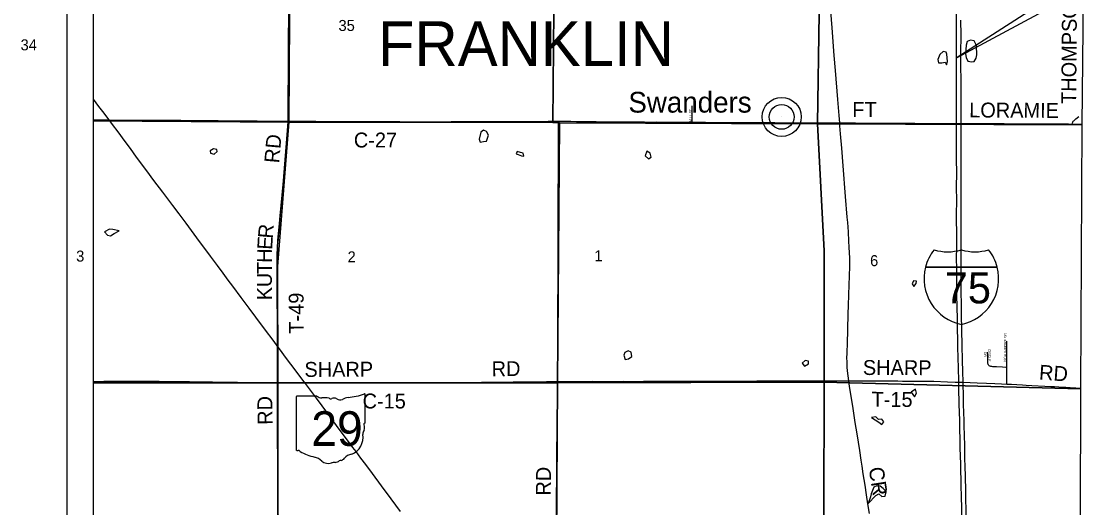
# Model space of a CAD drawing. Extents: x -784 to 1375, y -225 to 440.
# Drawn here: x 438.7 to 519.3, y 324.9 to 362 of the extents above; entities that cross this region are included whole.
import ezdxf

# ---------------------------------------------------------------- set-up
doc = ezdxf.new("R2010")
doc.units = 0
for name, color, linetype in [('GM_X_County_Road', 7, 'Continuous'), ('GM_X_County_Road_Text', 7, 'Continuous'), ('GM_X_Interstate_Location', 7, 'Continuous'), ('GM_X_Interstate_Route', 7, 'Continuous'), ('GM_X_Interstate_Shield', 7, 'Continuous'), ('GM_X_Minor_Lake', 7, 'Continuous'), ('GM_X_Section', 7, 'Continuous'), ('GM_X_Section_Text', 7, 'Continuous'), ('GM_X_State_Location', 7, 'Continuous'), ('GM_X_State_Route', 7, 'Continuous'), ('GM_X_State_Shield', 7, 'Continuous'), ('GM_X_Township', 7, 'Continuous'), ('GM_X_Township_Road', 7, 'Continuous'), ('GM_X_Township_Road_Text', 7, 'Continuous'), ('GM_X_Township_Subdivision', 7, 'Continuous'), ('GM_X_Township_Subdivision_Text', 7, 'Continuous'), ('GM_X_Township_Text', 7, 'Continuous'), ('GM_X_Unincorporated', 7, 'Continuous'), ('GM_X_Unincorporated_Location', 7, 'Continuous'), ('GM_X_Unincorporated_Text', 7, 'Continuous'), ('SH_Data', 7, 'Continuous'), ('SH_Text', 7, 'Continuous')]:
    doc.layers.add(name, color=color, linetype=linetype)

msp = doc.modelspace()

# ---------------------------------------------------------------- linework, layer by layer
at = {"layer": 'GM_X_County_Road'}
for points in [[(501.121, 354.211), (501.079, 354.768), (500.983, 356.007), (500.808, 358.2), (500.712, 359.339), (500.545, 361.445), (500.497, 362.077), (500.361, 363.774), (500.311, 364.381), (500.247, 365.161), (500.16, 366.276), (500.065, 367.403), (499.97, 368.604), (499.898, 369.459), (499.82, 370.487), (499.762, 371.134)], [(444.236, 354.441), (444.598, 354.437), (445.095, 354.439), (445.344, 354.439), (445.419, 354.437)], [(445.419, 354.437), (445.803, 354.43), (446.636, 354.421), (447.729, 354.417), (448.835, 354.416), (449.618, 354.418), (449.979, 354.42), (450.488, 354.414), (450.911, 354.41), (451.619, 354.406), (452.203, 354.396), (452.713, 354.391), (453.235, 354.387), (453.769, 354.386), (455.434, 354.372), (456.727, 354.361), (457.932, 354.353), (458.802, 354.352), (458.976, 354.349), (459.122, 354.347)], [(459.122, 354.347), (460.628, 354.338), (461.2, 354.334), (461.784, 354.33), (462.554, 354.325), (462.927, 354.324), (463.138, 354.324), (463.586, 354.323), (463.859, 354.322), (465.549, 354.314), (466.394, 354.314), (466.804, 354.313), (467.612, 354.31), (468.768, 354.304), (469.974, 354.306), (471.527, 354.31), (471.925, 354.31), (472.285, 354.31), (472.894, 354.317), (473.714, 354.313), (474.484, 354.313), (475.156, 354.314), (475.901, 354.314), (476.485, 354.323), (477.106, 354.328), (477.492, 354.33), (477.827, 354.33), (478.896, 354.332), (479.654, 354.332), (479.708, 354.332)], [(479.708, 354.332), (480.201, 354.335), (480.623, 354.333), (481.071, 354.328), (481.53, 354.324), (482.562, 354.31), (483.32, 354.303), (483.904, 354.299), (484.674, 354.293), (485.159, 354.29), (485.544, 354.287), (485.805, 354.284), (486.24, 354.281), (486.836, 354.28), (487.197, 354.281), (487.793, 354.277), (488.588, 354.268), (488.973, 354.26), (489.887, 354.257)], [(489.887, 354.257), (490.711, 354.257), (490.907, 354.256)], [(490.907, 354.256), (491.246, 354.255), (491.668, 354.253), (492.401, 354.253), (493.085, 354.253), (493.358, 354.25), (493.52, 354.246), (493.917, 354.247), (494.526, 354.24), (494.638, 354.238), (494.96, 354.236), (495.184, 354.237), (495.828, 354.236), (496.188, 354.233), (496.499, 354.23), (497.046, 354.223), (497.642, 354.222), (499.221, 354.222), (500.203, 354.219), (500.662, 354.216), (501.121, 354.211)], [(501.814, 334.565), (501.763, 334.947), (501.723, 335.318), (501.702, 335.603), (501.683, 335.976), (501.675, 336.337), (501.679, 336.623), (501.704, 337.53), (501.731, 338.325), (501.748, 338.847), (501.761, 339.282), (501.774, 339.692), (501.793, 340.288), (501.823, 341.145), (501.892, 343.281), (501.896, 343.628), (501.891, 343.926), (501.874, 344.323), (501.85, 344.757), (501.828, 345.191), (501.781, 345.923), (501.73, 346.617), (501.696, 347.038), (501.573, 348.611), (501.384, 350.94), (501.275, 352.278), (501.187, 353.38), (501.137, 353.987), (501.121, 354.211)], [(501.121, 354.211), (501.139, 354.211), (501.395, 354.209), (501.805, 354.208), (502.328, 354.206), (502.986, 354.202), (503.645, 354.198), (504.726, 354.192), (505.521, 354.188), (506.019, 354.182), (506.565, 354.18), (506.839, 354.183), (507.137, 354.176), (507.621, 354.171), (508.168, 354.172), (509.161, 354.168), (509.608, 354.166), (510.033, 354.164), (510.367, 354.163), (511.783, 354.158), (512.491, 354.155), (513, 354.156), (513.659, 354.155), (514.33, 354.148), (514.778, 354.145), (515.312, 354.145), (515.535, 354.144), (515.921, 354.143), (516.517, 354.139), (517.027, 354.136), (517.66, 354.134), (518.218, 354.132), (518.566, 354.13), (518.843, 354.126)], [(518.843, 354.126), (518.952, 354.125), (519.511, 354.121), (519.555, 354.12)], [(460.336, 334.419), (460.676, 334.426), (461.26, 334.424), (461.894, 334.424), (462.54, 334.424), (463.149, 334.421), (464.081, 334.419), (465.237, 334.413), (466.032, 334.415), (466.679, 334.417), (467.225, 334.422), (467.523, 334.422), (467.921, 334.424), (468.206, 334.422), (468.492, 334.421), (468.927, 334.42), (469.337, 334.419), (469.909, 334.423), (470.219, 334.422), (471.052, 334.429), (471.723, 334.432), (472.108, 334.44), (472.506, 334.439), (472.916, 334.441), (473.388, 334.448), (473.835, 334.45), (474.307, 334.457), (474.966, 334.467), (475.363, 334.469), (475.761, 334.475), (476.233, 334.479), (476.531, 334.487), (477.177, 334.491), (477.861, 334.494), (478.768, 334.504), (479.63, 334.514)], [(479.63, 334.514), (480.098, 334.52), (480.657, 334.524), (481.129, 334.52), (482.273, 334.526), (483.142, 334.525), (483.851, 334.523), (484.683, 334.529), (484.919, 334.524), (486.175, 334.53), (487.194, 334.542), (487.964, 334.539), (488.536, 334.539), (489.568, 334.536), (490.04, 334.536), (490.786, 334.539), (491.419, 334.544), (491.904, 334.546), (492.625, 334.547), (493.184, 334.549), (493.88, 334.551), (494.8, 334.553), (495.843, 334.56), (496.377, 334.568), (497.235, 334.565), (497.744, 334.559), (498.366, 334.555), (499.334, 334.558), (500.005, 334.563), (500.34, 334.565), (500.775, 334.569), (501.198, 334.574), (501.571, 334.574), (501.814, 334.565)], [(503.389, 324.459), (503.275, 325.183), (503.167, 325.871), (503.055, 326.608), (502.917, 327.479), (502.83, 328.057), (502.756, 328.523), (502.644, 329.26), (502.442, 330.524), (502.309, 331.384), (502.138, 332.464), (501.875, 334.146), (501.822, 334.503), (501.814, 334.565)]]:
    msp.add_lwpolyline(points, dxfattribs=at)
at = {"layer": 'GM_X_Interstate_Route'}
for points in [[(510.447, 323.738), (510.394, 325.826), (510.379, 326.496), (510.34, 328.236), (510.31, 329.441), (510.265, 331.553), (510.232, 332.796), (510.203, 334.038), (510.194, 334.462), (510.166, 335.641), (510.152, 336.25), (510.134, 337.206), (510.092, 339.008), (510.062, 340.462), (510.055, 340.847), (510.04, 342.102), (510.037, 343.121), (510.033, 343.879), (510.035, 344.773), (510.037, 345.482), (510.033, 347.184), (510.036, 348.352), (510.033, 349.26), (510.034, 350.453), (510.032, 351.397), (510.032, 353.212), (510.033, 354.164), (510.031, 355.237), (510.033, 356.666), (510.029, 358.133), (510.027, 358.779), (510.031, 359.922), (510.028, 361.588), (510.026, 362.706)], [(510.77, 324.222), (510.727, 326.049), (510.696, 327.391), (510.68, 327.925), (510.673, 328.198), (510.666, 328.484), (510.645, 329.478), (510.619, 330.559), (510.607, 331.018), (510.601, 331.279), (510.595, 331.553), (510.567, 332.758), (510.56, 333.019), (510.553, 333.304), (510.525, 334.45), (510.504, 335.267), (510.488, 336.125), (510.465, 337.28), (510.41, 339.591), (510.395, 340.275), (510.39, 340.585), (510.385, 341.132), (510.381, 341.468), (510.375, 342.226), (510.374, 342.885), (510.374, 343.531), (510.372, 344.016), (510.368, 345.345), (510.365, 345.929), (510.367, 347.619), (510.368, 348.117), (510.369, 348.589), (510.369, 348.937), (510.367, 349.546), (510.366, 350.117), (510.368, 350.813), (510.369, 351.236), (510.369, 351.348), (510.37, 351.621), (510.37, 351.845), (510.37, 351.894), (510.37, 352.093), (510.37, 353.211), (510.367, 354.163), (510.366, 355.66), (510.365, 356.356), (510.365, 357.101), (510.365, 357.362), (510.362, 358.642), (510.359, 359.09), (510.361, 359.525), (510.365, 360.892), (510.364, 362.035)]]:
    msp.add_lwpolyline(points, dxfattribs=at)
at = {"layer": 'GM_X_Interstate_Shield'}
for p, q in [((507.659, 343.215), (513.124, 343.215)), ((513.124, 343.215), (507.659, 343.215)), ((513.124, 343.215), (507.659, 343.215))]:
    msp.add_line(p, q, dxfattribs=at)
for centre, start, end in [((511.101, 342.345), 141.66896, 165.80665), ((509.353, 347.943), 253.00908, 286.99093), ((511.429, 347.943), 253.00908, 286.99093), ((509.681, 342.345), 14.19335, 38.33104), ((511.101, 342.345), 165.80665, 258.46304), ((509.681, 342.345), 281.53696, 14.19335)]:
    msp.add_arc(centre, 3.551, start, end, dxfattribs=at)
at = {"layer": 'GM_X_Minor_Lake'}
for p, q in [((453.139, 352.094), (453.188, 351.903)), ((453.685, 352.022), (453.657, 352.189)), ((476.537, 352.034), (476.466, 351.868)), ((477.062, 351.683), (476.99, 351.897)), ((486.745, 351.602), (486.682, 351.913)), ((476.466, 351.868), (476.631, 351.798)), ((506.65, 341.943), (506.768, 341.751)), ((506.939, 341.983), (506.965, 342.156)), ((484.676, 336.526), (484.769, 336.184)), ((498.257, 335.915), (498.45, 335.684)), ((498.735, 335.86), (498.731, 336.057)), ((504.487, 331.445), (504.339, 331.645))]:
    msp.add_line(p, q, dxfattribs=at)
for points in [[(511.553, 360.075), (511.498, 360.214), (511.358, 360.46), (511.093, 360.503), (510.833, 360.41), (510.76, 360.139), (510.709, 359.482)], [(510.709, 359.482), (510.758, 359.185), (510.897, 358.917), (511.178, 358.873), (511.376, 358.899), (511.525, 359.139), (511.567, 359.388), (511.553, 360.075)], [(509.286, 359.45), (509.237, 359.611), (508.995, 359.646), (508.74, 359.432), (508.601, 359.03)], [(508.601, 359.03), (508.66, 358.797), (508.896, 358.8), (509.17, 358.832), (509.265, 358.626), (509.323, 358.89), (509.286, 359.45)], [(474.362, 353.27), (474.215, 353.558), (473.973, 353.661), (473.781, 353.514), (473.659, 352.972)], [(473.659, 352.972), (473.714, 352.735), (473.973, 352.806), (474.217, 352.824), (474.362, 353.27)], [(453.657, 352.189), (453.392, 352.225), (453.139, 352.094)], [(453.188, 351.903), (453.453, 351.83), (453.685, 352.022)], [(476.99, 351.897), (476.793, 351.946), (476.537, 352.034)], [(486.682, 351.913), (486.427, 352.063), (486.31, 351.713)], [(476.631, 351.798), (476.865, 351.702), (477.062, 351.683)], [(486.31, 351.713), (486.545, 351.469), (486.745, 351.602)], [(446.226, 345.999), (445.741, 346.092), (445.491, 346.105), (445.1, 345.908)], [(445.1, 345.908), (445.331, 345.669), (445.566, 345.619), (445.834, 345.78), (446.226, 345.999)], [(506.965, 342.156), (506.738, 342.191), (506.65, 341.943)], [(506.768, 341.751), (506.939, 341.983)], [(485.28, 336.426), (485.228, 336.757), (485.009, 336.853), (484.756, 336.729), (484.676, 336.526)], [(484.769, 336.184), (485.036, 336.239), (485.28, 336.426)], [(498.731, 336.057), (498.481, 336.122), (498.257, 335.915)], [(498.45, 335.684), (498.735, 335.86)], [(506.976, 333.62), (506.888, 333.94), (506.556, 333.708)], [(506.556, 333.708), (506.809, 333.351), (506.976, 333.62)], [(504.339, 331.645), (504.072, 331.628), (503.87, 331.814), (503.553, 331.774)], [(503.553, 331.774), (504.091, 331.423), (504.339, 331.229), (504.487, 331.445)], [(504.67, 326.119), (504.443, 326.364), (504.195, 326.528), (503.952, 326.556), (503.715, 326.454), (503.627, 326.222), (503.516, 325.959), (503.458, 325.717), (503.297, 325.218)], [(503.297, 325.218), (503.871, 325.83), (504.109, 325.962), (504.341, 325.745), (504.592, 325.77), (504.67, 326.119)]]:
    msp.add_lwpolyline(points, dxfattribs=at)
at = {"layer": 'GM_X_Section'}
for p, q in [((444.236, 364.18), (444.236, 354.38)), ((444.236, 354.38), (444.236, 334.405)), ((444.236, 334.405), (444.236, 314.304))]:
    msp.add_line(p, q, dxfattribs=at)
for points in [[(506.617, 371.896), (519.776, 373.558), (519.562, 354.071), (499.42, 354.13), (499.684, 371.026)], [(499.684, 371.026), (499.42, 354.13), (479.771, 354.211), (479.249, 354.244), (479.388, 368.483), (486.548, 369.394)], [(466.358, 366.879), (479.388, 368.483), (479.249, 354.244), (459.168, 354.279), (459.245, 366.065)], [(459.168, 354.279), (479.249, 354.244), (479.771, 354.211), (479.62, 334.419), (458.333, 334.409), (458.294, 343.266)], [(479.771, 354.211), (499.42, 354.13), (499.944, 344.47), (499.931, 334.47), (479.62, 334.419)], [(519.562, 354.071), (519.48, 333.952), (499.931, 334.47), (499.944, 344.47), (499.42, 354.13)], [(458.333, 334.409), (479.62, 334.419), (479.486, 314.324), (458.351, 314.341)], [(479.62, 334.419), (499.931, 334.47), (499.901, 324.411), (499.543, 314.191), (479.486, 314.324)], [(519.48, 333.952), (519.411, 314.122), (499.543, 314.191), (499.901, 324.411), (499.931, 334.47)]]:
    msp.add_lwpolyline(points, close=True, dxfattribs=at)
for points in [[(444.236, 354.38), (459.168, 354.279), (459.245, 366.065), (446.077, 364.411), (444.236, 364.18)], [(444.236, 334.405), (458.333, 334.409), (458.294, 343.266), (459.168, 354.279), (444.236, 354.38)], [(444.236, 314.304), (458.351, 314.341), (458.333, 334.409), (444.236, 334.405)]]:
    msp.add_lwpolyline(points, dxfattribs=at)
at = {"layer": 'GM_X_State_Route'}
for points in [[(444.236, 356.029), (444.649, 355.468), (444.937, 355.078), (445.34, 354.542), (445.419, 354.437), (445.609, 354.184), (446.186, 353.421), (446.577, 352.89), (447.042, 352.261), (447.523, 351.612), (448.31, 350.555), (448.843, 349.837), (449.521, 348.932), (450.273, 347.927), (450.758, 347.281), (451.294, 346.564), (452.109, 345.467), (453.148, 344.071), (453.682, 343.353), (454.11, 342.773), (454.502, 342.244), (454.852, 341.776), (455.49, 340.919), (456.097, 340.101), (456.617, 339.403), (457.349, 338.414), (457.913, 337.657), (458.303, 337.136), (458.405, 337.001), (458.952, 336.276), (459.599, 335.41), (460.336, 334.419)], [(444.236, 334.518), (445.041, 334.526), (445.775, 334.531), (448.16, 334.544), (449.266, 334.538), (450.397, 334.522), (451.031, 334.515), (451.578, 334.509), (452.149, 334.498), (452.745, 334.488), (453.317, 334.484), (455.231, 334.467), (457.853, 334.436), (458.321, 334.433), (459.133, 334.43), (460.177, 334.421), (460.336, 334.419)], [(460.336, 334.419), (460.378, 334.363), (460.842, 333.748), (461.218, 333.238), (461.655, 332.65), (462.22, 331.893), (462.965, 330.882), (463.58, 330.054), (464.008, 329.49), (464.248, 329.173), (464.618, 328.675), (464.975, 328.196), (465.493, 327.498), (466.187, 326.558), (466.924, 325.573), (467.27, 325.102), (467.638, 324.602)]]:
    msp.add_lwpolyline(points, dxfattribs=at)
at = {"layer": 'GM_X_State_Shield'}
for p, q in [((461.29, 333.399), (459.745, 333.399)), ((464.967, 331.404), (464.967, 333.498)), ((459.693, 333.33), (459.693, 329.327)), ((464.966, 331.405), (464.967, 331.404))]:
    msp.add_line(p, q, dxfattribs=at)
for centre, radius, start, end in [((459.754, 333.338), 0.0611, 98.1301, 188.1301), ((461.657, 333.863), 0.593, 231.61951, 271.11188), ((463.088, 338.855), 5.592, 275.84447, 288.90645), ((464.908, 333.507), 0.0587, 351.86209, 97.738), ((461.854, 331.152), 2.127, 80.48669, 94.98827), ((462.337, 333.359), 0.171, 219.79206, 297.10237), ((462.588, 332.896), 0.355, 54.46668, 119.14113), ((463.046, 333.531), 0.428, 233.85621, 294.82819), ((463.802, 332.176), 1.125, 97.34618, 120.76885), ((464.953, 331.25), 0.0909, 107.94398, 210.33697), ((464.375, 330.986), 0.545, 340.03296, 23.64957), ((464.904, 331.396), 0.0628, 289.60381, 7.73413), ((463.402, 330.262), 1.399, 292.30889, 8.98584), ((465.177, 330.528), 0.397, 136.8065, 186.92959), ((459.754, 329.319), 0.0616, 171.95839, 258.30661), ((459.764, 329.728), 0.47, 267.33899, 280.60386), ((459.86, 329.097), 0.17, 29.74838, 93.27175), ((462.001, 332.692), 4.038, 240.41292, 257.1985), ((460.797, 327.529), 1.264, 47.18416, 75.83597), ((463.021, 328.939), 0.452, 282.87319, 323.27711), ((463.991, 328.204), 0.766, 94.40312, 142.57675), ((462.164, 329.077), 0.802, 230.70037, 286.29184), ((462.627, 327.693), 0.659, 85.69512, 111.20995), ((462.686, 328.777), 0.427, 268.77702, 315.54927), ((463.072, 328.389), 0.12, 65.75173, 132.64842)]:
    msp.add_arc(centre, radius, start, end, dxfattribs=at)
at = {"layer": 'GM_X_Township'}
for points in [[(444.236, 382.734), (444.236, 283.309), (458.267, 283.309)], [(458.267, 283.309), (458.263, 284.231), (458.296, 294.134), (458.336, 314.323), (458.289, 334.394), (458.283, 337.182), (458.257, 342.903), (458.257, 344.192), (458.276, 344.705), (458.316, 345.264), (458.426, 346.547), (458.496, 347.13), (458.717, 349.506), (458.868, 351.4), (458.971, 352.658), (459.085, 354.3), (459.121, 359.929), (459.158, 366.091), (446.019, 364.376), (446.293, 382.704), (444.236, 382.734)], [(458.336, 314.323), (458.289, 334.394), (458.283, 337.182), (458.257, 342.903), (458.257, 344.192), (458.276, 344.705), (458.316, 345.264), (458.426, 346.547), (458.496, 347.13), (458.717, 349.506), (458.868, 351.4), (458.971, 352.658), (459.085, 354.3), (459.121, 359.929), (459.158, 366.091)]]:
    msp.add_lwpolyline(points, dxfattribs=at)
at = {"layer": 'GM_X_Township_Road'}
for points in [[(459.122, 354.347), (459.133, 354.603), (459.139, 354.988), (459.143, 356.056), (459.148, 357.237), (459.152, 358.169), (459.154, 359.251), (459.16, 359.922), (459.163, 360.581), (459.167, 361.326), (459.167, 362.122), (459.171, 362.719), (459.175, 363.539), (459.176, 364.247), (459.178, 364.956), (459.177, 365.615), (459.185, 365.938), (459.189, 366.105)], [(458.303, 337.136), (458.305, 337.373), (458.306, 337.535), (458.31, 338.119), (458.313, 338.927), (458.306, 340.393), (458.304, 341.027), (458.302, 341.437), (458.297, 342.021), (458.296, 342.616), (458.296, 343.028), (458.295, 344.321), (458.302, 344.632), (458.317, 344.894), (458.357, 345.365), (458.427, 346.169), (458.518, 347.209), (458.593, 348.076), (458.695, 349.265), (458.756, 349.958), (458.808, 350.553), (458.908, 351.729), (458.966, 352.46), (459.019, 353.08), (459.078, 353.761), (459.121, 354.318), (459.122, 354.347)], [(479.63, 334.514), (479.641, 335.413), (479.642, 336.171), (479.643, 337.153), (479.643, 337.911), (479.641, 338.346), (479.654, 340.135), (479.654, 340.645), (479.659, 341.701), (479.656, 343.601), (479.656, 343.984), (479.661, 344.555), (479.667, 345.908), (479.669, 346.579), (479.665, 347.163), (479.669, 347.735), (479.675, 348.394), (479.678, 349.176), (479.684, 349.996), (479.69, 351.524), (479.69, 351.947), (479.701, 352.841), (479.7, 353.561), (479.7, 353.885), (479.706, 354.234), (479.708, 354.332)], [(518.843, 354.126), (518.868, 354.224), (518.876, 354.258), (518.895, 354.3), (518.922, 354.338), (518.953, 354.374), (519.016, 354.431), (519.122, 354.516), (519.334, 354.691)], [(458.332, 331.994), (458.331, 332.034), (458.325, 332.767), (458.319, 333.127), (458.317, 333.637), (458.317, 334.047), (458.319, 334.308), (458.321, 334.433)], [(479.615, 333.175), (479.615, 333.201), (479.624, 333.872), (479.63, 334.514)], [(501.814, 334.565), (501.898, 334.562), (502.01, 334.559), (502.519, 334.56), (502.892, 334.561), (503.19, 334.562), (503.737, 334.566), (504.433, 334.565), (505.067, 334.556), (505.539, 334.552), (505.899, 334.548), (506.508, 334.544), (506.757, 334.542), (507.094, 334.543)], [(507.094, 334.543), (507.179, 334.543), (507.936, 334.536), (508.296, 334.527), (509.326, 334.494), (509.909, 334.473), (510.194, 334.462), (510.525, 334.45), (511.598, 334.416), (512.318, 334.382), (512.951, 334.358), (513.46, 334.337), (513.851, 334.32)], [(513.851, 334.32), (513.919, 334.317), (514.205, 334.302), (514.614, 334.286), (515.049, 334.264), (515.334, 334.245), (515.756, 334.221), (516.761, 334.164), (517.22, 334.14), (517.48, 334.124), (517.828, 334.105), (518.125, 334.087), (518.361, 334.07), (518.671, 334.054), (519.105, 334.03), (519.417, 334.015)], [(479.474, 314.385), (479.477, 315.506), (479.479, 315.953), (479.481, 316.512), (479.486, 317.83), (479.492, 318.762), (479.499, 319.482), (479.51, 321.085), (479.521, 322.365), (479.53, 323.198), (479.538, 324.167), (479.55, 325.509), (479.566, 327.436), (479.573, 327.994), (479.579, 329.051), (479.598, 330.84), (479.615, 333.175)], [(458.339, 324.478), (458.336, 325.087), (458.335, 325.945), (458.333, 326.517), (458.334, 326.889), (458.333, 327.225), (458.333, 327.597), (458.335, 328.095), (458.337, 329.313), (458.341, 330.12), (458.342, 330.816), (458.341, 331.338), (458.332, 331.994)]]:
    msp.add_lwpolyline(points, dxfattribs=at)
at = {"layer": 'GM_X_Township_Subdivision'}
for points in [[(489.887, 354.257), (489.884, 354.778), (489.876, 355.237), (489.868, 355.51)], [(513.854, 335.586), (513.851, 335.906), (513.854, 336.352), (513.857, 336.6), (513.858, 336.972), (513.857, 337.58)], [(513.854, 335.586), (513.773, 335.59), (513.518, 335.602), (513.059, 335.623), (512.858, 335.635), (512.787, 335.641), (512.717, 335.646), (512.643, 335.656), (512.594, 335.669), (512.549, 335.688), (512.517, 335.708), (512.489, 335.732), (512.458, 335.771), (512.439, 335.803), (512.425, 335.837), (512.413, 335.881), (512.405, 335.927), (512.402, 336.007), (512.401, 336.326), (512.397, 336.656), (512.393, 336.759)], [(513.851, 334.32), (513.852, 334.442), (513.852, 334.641), (513.856, 335.286), (513.854, 335.586)]]:
    msp.add_lwpolyline(points, dxfattribs=at)
at = {"layer": 'GM_X_Unincorporated'}
for radius in [1.488, 0.943]:
    msp.add_circle((496.7, 354.669), radius, dxfattribs=at)
at = {"layer": 'GM_X_Unincorporated_Location'}
msp.add_line((496.7, 354.669), (496.7, 354.669), dxfattribs=at)
at = {"layer": 'SH_Data'}
for p, q in [((442.236, 421.309), (442.236, 281.309)), ((444.236, 419.309), (444.236, 283.309))]:
    msp.add_line(p, q, dxfattribs=at)
at = {"layer": 'SH_Text'}
msp.add_lwpolyline([(532.832, 373.821), (510.073, 359.188), (532.832, 371.439)], close=True, dxfattribs=at)

# ---------------------------------------------------------------- texts
at = {"layer": 'GM_X_County_Road_Text'}
for s, rotation, p in [('FT', 0.00001, (502.083, 354.661)), ('LORAMIE', 359.69837, (510.987, 354.628)), ('C-27', 0.00001, (464.1, 352.34)), ('SHARP', 0.21165, (460.335, 334.862)), ('RD', 0.49451, (474.603, 334.911)), ('C-15', 0.00001, (464.767, 332.457)), ('CR', 278.78439, (503.325, 327.916))]:
    msp.add_text(s, height=1.1364, rotation=rotation, dxfattribs=at).set_placement(p)
at = {"layer": 'GM_X_Interstate_Location'}
for s in ['-', '.', ',']:
    msp.add_text(s, height=0.00379, dxfattribs=at).set_placement((510.39, 341.704))
msp.add_text('75', height=0.00379, rotation=0.00001, dxfattribs=at).set_placement((509.617, 340.92))
at = {"layer": 'GM_X_Interstate_Shield'}
msp.add_text('75', height=2.3674, dxfattribs=at).set_placement((509.126, 340.463))
at = {"layer": 'GM_X_Section_Text'}
for s, height, p in [('35', 0.8371, (462.928, 361.216)), ('34', 0.8371, (438.703, 359.741)), ('3', 0.837, (442.937, 343.649)), ('2', 0.837, (463.62, 343.589)), ('1', 0.837, (482.428, 343.674)), ('6', 0.837, (503.436, 343.299))]:
    msp.add_text(s, height=height, rotation=0.00001, dxfattribs=at).set_placement(p)
at = {"layer": 'GM_X_State_Location'}
for s in ['s', 'r']:
    msp.add_text(s, height=0.00379, dxfattribs=at).set_placement((462.271, 331.063))
msp.add_text('29', height=0.00379, rotation=0.00001, dxfattribs=at).set_placement((461.317, 330.787))
at = {"layer": 'GM_X_State_Shield'}
msp.add_text('29', height=2.6367, dxfattribs=at).set_placement((460.856, 329.61))
at = {"layer": 'GM_X_Township_Road_Text'}
for s, height, rotation, p in [('THOMPSON', 1.1364, 89.50394, (519.136, 355.65)), ('RD', 1.1364, 85.07166, (458.404, 351.113)), ('R', 1.136, 85.11546, (457.918, 345.371)), ('E', 1.136, 86.6982, (457.869, 344.53)), ('H', 1.136, 89.03823, (457.853, 343.543)), ('T', 1.136, 89.99142, (457.853, 342.698)), ('U', 1.136, 90, (457.853, 341.698)), ('K', 1.136, 90, (457.853, 340.698)), ('T-49', 1.1364, 90.35597, (460.289, 338.162)), ('SHARP', 1.1364, 359.78777, (502.885, 335.012)), ('RD', 1.1364, 356.14842, (516.285, 334.66)), ('T-15', 1.1364, 359.64407, (503.546, 332.592)), ('RD', 1.1364, 90.49345, (457.903, 331.218)), ('RD', 1.1364, 89.50635, (479.103, 325.818))]:
    msp.add_text(s, height=height, rotation=rotation, dxfattribs=at).set_placement(p)
at = {"layer": 'GM_X_Township_Subdivision_Text'}
for s, height, rotation, p in [('MILL ST', 0.1894, 90, (489.848, 354.281)), ('NORTHMORE DR', 0.18939, 89.49728, (513.814, 336.032)), ('DR', 0.1894, 270, (512.113, 336.765)), ('CIRCLE', 0.1894, 270, (512.436, 336.998))]:
    msp.add_text(s, height=height, rotation=rotation, dxfattribs=at).set_placement(p)
at = {"layer": 'GM_X_Township_Text'}
msp.add_text('FRANKLIN', height=3.4091, rotation=0.00001, dxfattribs=at).set_placement((465.939, 358.545))
at = {"layer": 'GM_X_Unincorporated_Text'}
msp.add_text('Swanders', height=1.5795, rotation=0.00001, dxfattribs=at).set_placement((485.017, 354.997))

doc.saveas('drawing.dxf')
